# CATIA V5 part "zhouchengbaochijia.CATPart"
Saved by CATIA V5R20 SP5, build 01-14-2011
Part number: Part2
Bounding box of the stored display mesh (mm): x -100 to 100, y -99.999 to 99.999, z -2.5 to 19.843
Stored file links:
  E:\180522127 徐丽维\zhouchengbaochijia.CATPart
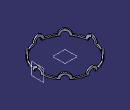
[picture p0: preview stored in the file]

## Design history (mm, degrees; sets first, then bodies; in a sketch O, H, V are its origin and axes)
Set1
  Sketch1 on xy-plane, origin (0, 0, 0), H (1, 0, 0), V (0, 1, 0)
    circle A1 centre (0, 0) radius 100
    radius A1 = 100
Body1 (main body)
  Pad1: profile Sketch1, direction (0, 0, 1), length 2.5, mirrored extent, thin wall 5
  Body2
    Sketch2 on xy-plane, origin (0, 0, 0), H (1, 0, 0), V (0, 1, 0)
      arc A1 centre (97.5, 0) radius 20 from (97.5, -20) to (97.5, 20) ccw
      point P1 (97.5, 0)
      point P2 (117.5, 0)
      axis line L1 (97.5, 50) -> (97.5, -50)
      point P5 (97.5, 20)
      point P6 (97.5, -20)
      radius A1 = 20
      distance V P1 = 97.5
      coincidence: P1 H, A1 P2, P2 H, L1 P5, L1 P6
      vertical: L1 V
    Shaft1: profile Sketch2, axis Sketch2.L1, angle 360
    CircPattern1: of the body so far, instances 8, angular step 45, axis from end face of Pad1
    Sketch3 on xy-plane, origin (0, 0, 0), H (1, 0, 0), V (0, 1, 0)
      circle A1 centre (0, 0) radius 95
      radius A1 = 95
    Pocket1: profile Sketch3, direction (0, 0, -1), length 50, mirrored extent
    Split1: SplitPlane start face of Pad1
    Sketch4 on xy-plane, origin (0, 0, 0), H (1, 0, 0), V (0, 1, 0)
      circle A1 centre (0, 0) radius 100
      radius A1 = 100
    Pocket2: profile Sketch4, direction (0, 0, -1), length 50, mirrored extent, outer side
  Assemble1: tool Body2
  Body3
    Plane1: type Offset, RefPlane yz-plane, Offset 97.5
    Sketch5 on Plane1, origin (97.5, 0, 0), H (0, 1, 0), V (0, 0, 1)
      arc A1 centre (0, 0) radius 12 from (-12, 0) to (12, 0) ccw
      axis line L1 (-30, 0) -> (40, 0)
      point P1 (-30, 0)
      point P3 (-12, 0)
      point P4 (12, 0)
      radius A1 = 12
      coincidence: P1 H, L1 P4, L1 P3
      horizontal: L1 H
    Shaft2: profile Sketch5, axis Sketch5.L1, angle 360
    CircPattern2: of Shaft2, instances 8, angular step 45, axis from face of Pad1
  Remove1: tool Body3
